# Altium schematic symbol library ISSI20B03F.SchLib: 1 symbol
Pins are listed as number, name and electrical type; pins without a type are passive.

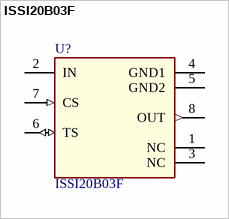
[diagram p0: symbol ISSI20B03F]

## ISSI20B03F
designator U?
coreless-transformer advanced solid-state isolators; Manufacturer: Infineon Technologies
pins: 1 NC "Not connected", 2 IN (power) "Supply and non-inverting control input", 3 NC "Not connected", 4 GND1 (power) "Reference of control side", 5 GND2 (power) "Reference of output side", 6 TS (io) "Output for temperature sensor bias current and input for temperature signal", 7 CS (in) "Input for current-sense signal", 8 OUT (out) "Gate drive output"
